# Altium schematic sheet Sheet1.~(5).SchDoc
size A3
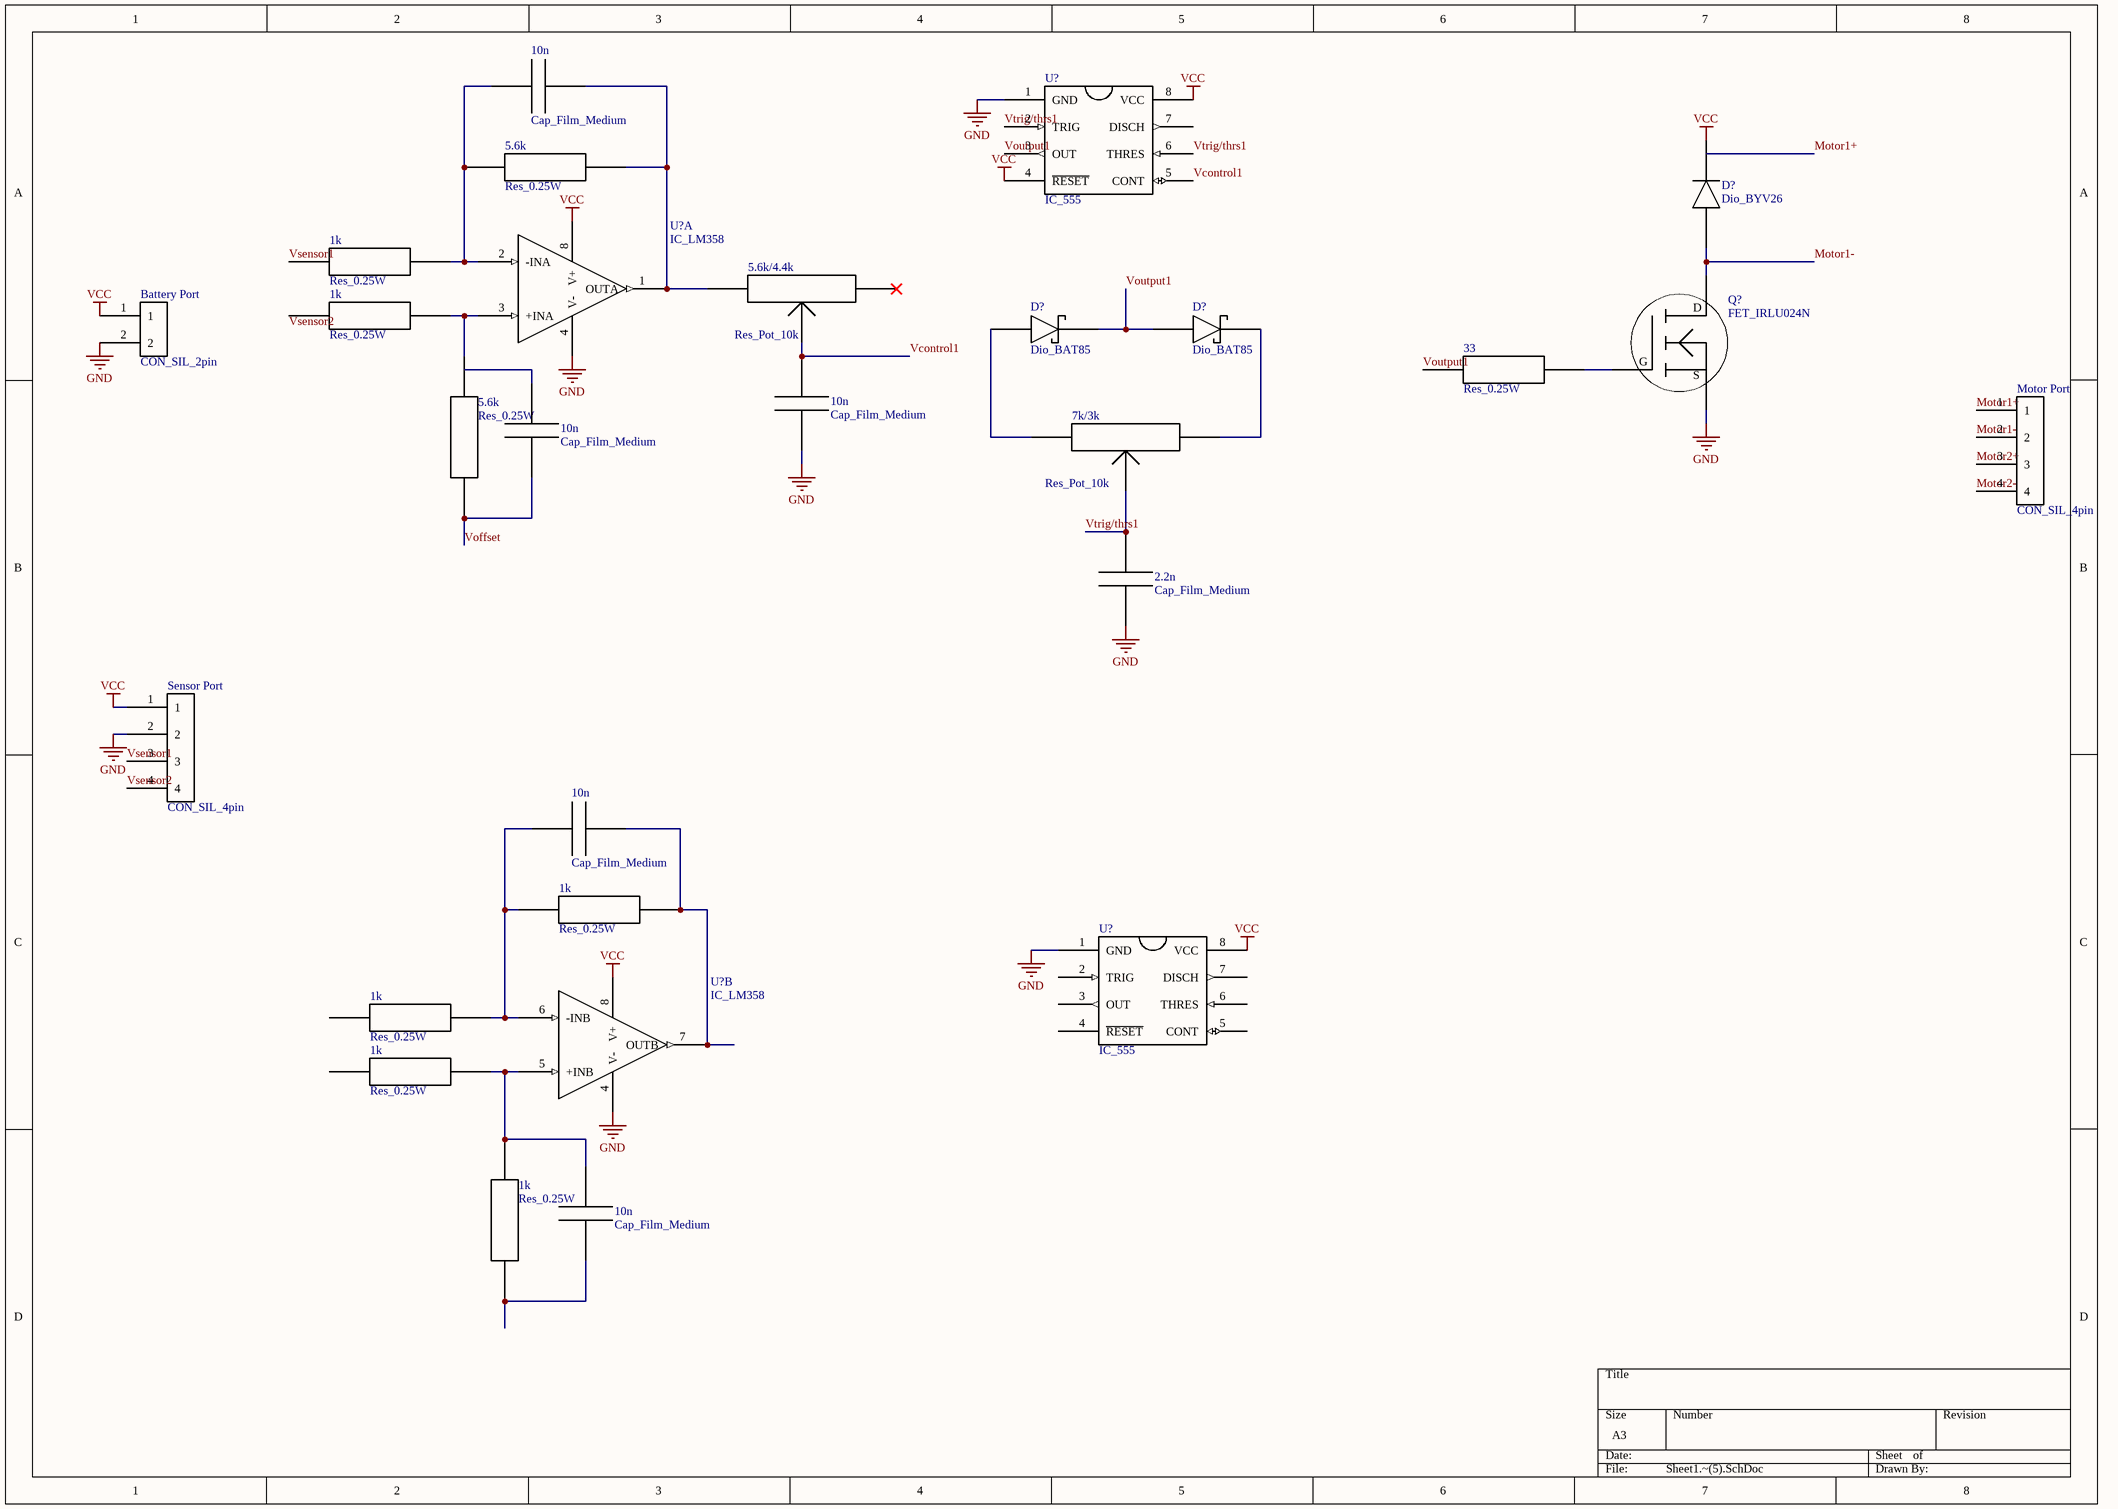
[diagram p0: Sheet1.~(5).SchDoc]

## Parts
(Parts that share a designator on the sheet are numbered #1, #2 ... from top to bottom, then left to right.)
1k#1  Res_0.25W  [Resistor_400mil_pitch]
1k#2  Res_0.25W  [Resistor_400mil_pitch]
1k#3  Res_0.25W  [Resistor_400mil_pitch]
1k#4  Res_0.25W  [Resistor_400mil_pitch]
1k#5  Res_0.25W  [Resistor_400mil_pitch]
1k#6  Res_0.25W  [Resistor_400mil_pitch]
2.2n  Cap_Film_Medium  [CAP_FILM_3.2mm]
5.6k#1  Res_0.25W  [Resistor_400mil_pitch]
5.6k#2  Res_0.25W  [Resistor_400mil_pitch]
5.6k/4.4k  Res_Pot_10k  [POT]
7k/3k  Res_Pot_10k  [POT]
10n#1  Cap_Film_Medium  [CAP_FILM_3.2mm]
10n#2  Cap_Film_Medium  [CAP_FILM_3.2mm]
10n#3  Cap_Film_Medium  [CAP_FILM_3.2mm]
10n#4  Cap_Film_Medium  [CAP_FILM_3.2mm]
10n#5  Cap_Film_Medium  [CAP_FILM_3.2mm]
33  Res_0.25W  [Resistor_400mil_pitch]
Battery_Port  CON_SIL_2pin  [ece-HDR1X2]
D?#1  Dio_BYV26  [SOD_47]
D?#2  Dio_BAT85  [Diode_SmallSignal]
D?#3  Dio_BAT85  [Diode_SmallSignal]
Motor_Port  CON_SIL_4pin  [ece-HDR1X4]
Q?  FET_IRLU024N  [TO_251AA]
Sensor_Port  CON_SIL_4pin  [ece-HDR1X4]
U?#1  IC_555  [DIP_8]
U?#2  IC_LM358  [DIP_8]  (part A of 2)
U?#3  IC_555  [DIP_8]
U?#4  IC_LM358  [DIP_8]  (part B of 2)

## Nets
GND: 2.2n.2 10n#2.2 Battery_Port.2 Q?.3(S) Sensor_Port.2 U?#1.1(GND) U?#2.4(V-) U?#3.1(GND) U?#4.4(V-)
VCC: Battery_Port.1 D?#1.2 Sensor_Port.1 U?#1.4(~{RESET}) U?#1.8(VCC) U?#2.8(V+) U?#3.8(VCC) U?#4.8(V+)
Motor1+: Motor_Port.1
Motor1-: D?#1.1 Motor_Port.2 Q?.1(D)
Motor2+: Motor_Port.3
Motor2-: Motor_Port.4
Vcontrol1: 5.6k/4.4k.2 10n#2.1 U?#1.5(CONT)
Voffset: 5.6k#2.1 10n#3.1
Voutput1: 33.2 D?#2.2 D?#3.1 U?#1.3(OUT)
Vsensor1: 1k#1.1 Sensor_Port.3
Vsensor2: Sensor_Port.4
Vtrig/thrs1: 2.2n.1 7k/3k.2 U?#1.2(TRIG) U?#1.6(THRES)
Net1k#1_2: 1k#1.2 5.6k#1.1 10n#1.1 U?#2.2(-INA)
Net1k#2_2: 1k#2.2 5.6k#2.2 U?#2.3(+INA)
Net1k#3_1: 1k#3.1 1k#4.2 10n#4.2 U?#4.6(-INB)
Net1k#3_2: 1k#3.2 10n#4.1 U?#4.7(OUTB)
Net1k#5_2: 1k#5.2 1k#6.2 10n#5.2 U?#4.5(+INB)
Net1k#6_1: 1k#6.1 10n#5.1
Net5.6k#1_2: 5.6k#1.2 5.6k/4.4k.3 10n#1.2 U?#2.1(OUTA)
Net7k/3k_1: 7k/3k.1 D?#3.2
Net7k/3k_3: 7k/3k.3 D?#2.1
Net33_1: 33.1 Q?.2(G)

Not connected (* = marked no-connect by the designer): 1k#2 1; 1k#4 1; 1k#5 1; 5.6k/4.4k 1*; 10n#3 2; U?#1 7(DISCH); U?#3 2(TRIG) 3(OUT) 4(~{RESET}) 5(CONT) 6(THRES) 7(DISCH)

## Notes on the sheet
- Labels drawn without touching a wire or pin: Vsensor2

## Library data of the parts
2.2n 10n#1-10n#5 = Cap_Film_Medium: Cap_Ceramic
Battery_Port = CON_SIL_2pin: 2 pin in line connector
D?#1 = Dio_BYV26: BYV26
Motor_Port Sensor_Port = CON_SIL_4pin: 4 pin in line connector
Q? = FET_IRLU024N: N-Chan MOSFET 55V 17A 65mOhm
U?#1 U?#3 = IC_555: NEC555
U?#2 U?#4 = IC_LM358: LM358 - Dual Opamp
